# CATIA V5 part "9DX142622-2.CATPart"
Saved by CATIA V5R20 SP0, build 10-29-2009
Part number: 9DX142622-2
Revision: ANY
Definition: UNKNOWN
Nomenclature: 9DX142622-2
Source: Unknown
Bounding box of the stored display mesh (mm): x -15 to 15, y 0 to 34.5, z -15 to 15
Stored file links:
  C:\Users\Utente\Desktop\IO LAVORO\3D X SITO CF\CUMSA\3D files DX\DX 142622\9DX142622-2.CATPart
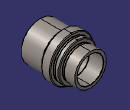
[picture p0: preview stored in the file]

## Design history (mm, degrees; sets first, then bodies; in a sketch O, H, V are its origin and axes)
Body1 "Revolución1" (main body)
  Solid1: solid without history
